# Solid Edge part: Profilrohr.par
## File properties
Username: bmolnar
Dokumentum tartalom típus: 0
Author: bmolnar
Last saved by: bmolnar
Revision: 82
Sűrűség: 0,000 kg/m^3
Pontosság: 0,990
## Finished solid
Body 1: solid body, 115 faces, 338 edges, 224 vertices.
  Faces by surface: cylinder 59, plane 56
  Edges by curve: line 220, circle 118
Bounding box of the edges (mm): 95.500 x 95.500 x 64.000, from (-47.75, -47.75, -35) to (47.75, 47.75, 29).
Cylindrical faces by radius (mm): R0.2 x24, R0.5 x24, R1 x4, R10 x4, R13.5 x2, R40 x1
Planar faces by outward normal: +x 13, +y 14, +z 1, -x 13, -y 14, -z 1
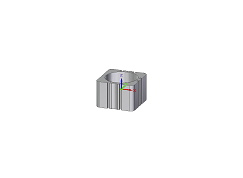
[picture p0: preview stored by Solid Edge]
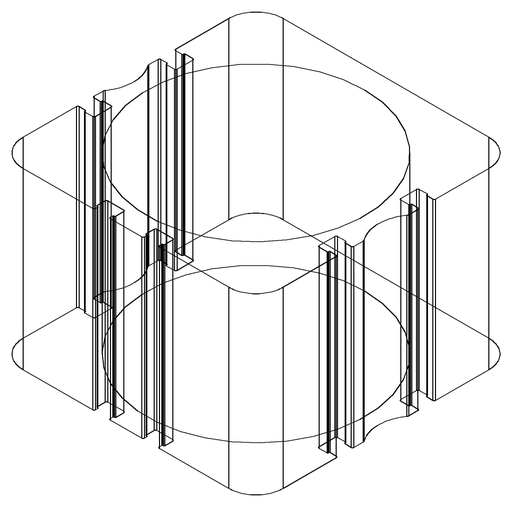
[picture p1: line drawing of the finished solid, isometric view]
